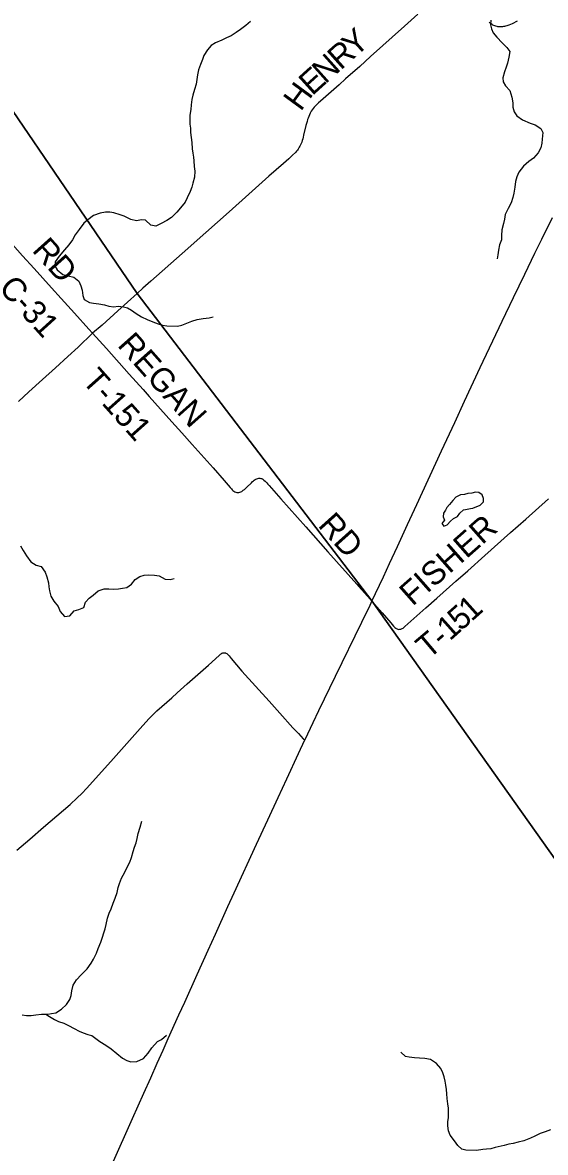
# Model space of a CAD drawing. Extents: x 0 to 34, y 0 to 22.
# Drawn here: x 27.52 to 28.78, y 16.977 to 19.7 of the extents above; entities that cross this region are included whole.
import ezdxf

# ---------------------------------------------------------------- set-up
doc = ezdxf.new("R2010")
doc.units = 0
for name, color, linetype in [('GM_X_Corporation', 7, 'Continuous'), ('GM_X_County_Road', 7, 'Continuous'), ('GM_X_County_Road_Text', 7, 'Continuous'), ('GM_X_Minor_Lake', 7, 'Continuous'), ('GM_X_Minor_River', 7, 'Continuous'), ('GM_X_State_Route', 7, 'Continuous'), ('GM_X_Township_Road', 7, 'Continuous'), ('GM_X_Township_Road_Text', 7, 'Continuous')]:
    doc.layers.add(name, color=color, linetype=linetype)

msp = doc.modelspace()

# ---------------------------------------------------------------- linework, layer by layer
at = {"layer": 'GM_X_Corporation'}
for points in [[(31.5875, 16.2767), (31.5875, 21.1059), (25.6086, 21.1059), (25.0178, 20.9472), (26.0175, 20.4289), (26.9873, 19.9283), (27.122, 19.8586), (27.3085, 19.7612), (27.7955, 19.0474), (28.3618, 18.3058), (29.4482, 16.7745), (29.7308, 16.376), (30.2965, 15.5727), (30.4064, 15.4161), (30.5426, 15.5161)], [(24.7875, 21.0754), (24.7875, 14.3059), (28.9316, 14.3059), (29.0116, 14.3654), (30.2271, 15.2782), (30.4064, 15.4161), (30.2965, 15.5727), (29.7308, 16.376), (29.4482, 16.7745), (28.3618, 18.3058), (27.7955, 19.0474), (27.3085, 19.7612), (27.122, 19.8586), (26.9873, 19.9283), (26.0175, 20.4289), (25.0178, 20.9472)]]:
    msp.add_lwpolyline(points, close=True, dxfattribs=at)
at = {"layer": 'GM_X_County_Road'}
for points in [[(28.4727, 19.7202), (28.4404, 19.6911), (28.3588, 19.6183), (28.3324, 19.5946), (28.2986, 19.5643), (28.2829, 19.5503), (28.238, 19.511), (28.2334, 19.5068), (28.2303, 19.5038), (28.2276, 19.501), (28.2251, 19.4985), (28.2229, 19.496), (28.2203, 19.4929), (28.2178, 19.4894), (28.2157, 19.4864), (28.2131, 19.4816), (28.2112, 19.4777), (28.2097, 19.4738), (28.2081, 19.4697), (28.2069, 19.4661), (28.2056, 19.462), (28.2029, 19.4518), (28.1973, 19.4283), (28.1961, 19.4239), (28.1951, 19.4198), (28.1939, 19.416), (28.1927, 19.412), (28.1913, 19.4085), (28.1897, 19.4051), (28.1884, 19.4022), (28.1867, 19.3995), (28.1857, 19.3978), (28.1841, 19.3953), (28.1822, 19.3928), (28.1802, 19.3903), (28.1774, 19.387), (28.1707, 19.3804), (28.1615, 19.372), (28.149, 19.3607), (28.1136, 19.3295), (28.0653, 19.2865), (28.0174, 19.2441), (27.9613, 19.194), (27.9046, 19.1437), (27.8289, 19.0764), (27.8098, 19.0596), (27.7958, 19.0469)], [(28.7119, 19.7035), (28.6997, 19.6973), (28.6922, 19.694), (28.6894, 19.693), (28.6869, 19.6921), (28.684, 19.6914), (28.6818, 19.6907), (28.6795, 19.6903), (28.677, 19.69), (28.6748, 19.6898), (28.6725, 19.6897), (28.6703, 19.6898), (28.6681, 19.6898), (28.6658, 19.6901), (28.6637, 19.6904), (28.6606, 19.6912), (28.6581, 19.6921), (28.6558, 19.6929), (28.6536, 19.694), (28.6515, 19.6953), (28.6492, 19.6968), (28.6469, 19.6987), (28.6449, 19.7004)], [(27.6884, 18.9512), (27.6794, 18.9612), (27.6446, 19), (27.6128, 19.035), (27.5895, 19.0608), (27.5681, 19.0842), (27.5474, 19.1073), (27.5192, 19.138), (27.4952, 19.165), (27.4895, 19.1714), (27.4847, 19.177), (27.4802, 19.1823), (27.4762, 19.1874), (27.4722, 19.1925), (27.4673, 19.1992), (27.4623, 19.206), (27.4369, 19.242), (27.4167, 19.2704), (27.3758, 19.3283), (27.3261, 19.3981), (27.2789, 19.4652), (27.2719, 19.4757)], [(27.7958, 19.0469), (27.7493, 19.0051), (27.7115, 18.9709), (27.6884, 18.9512)]]:
    msp.add_lwpolyline(points, dxfattribs=at)
at = {"layer": 'GM_X_Minor_Lake'}
for points in [[(28.5567, 18.5484), (28.5489, 18.5386), (28.5428, 18.531), (28.5393, 18.525), (28.5346, 18.5175), (28.5341, 18.5083), (28.5371, 18.5003), (28.5309, 18.4928), (28.5354, 18.4863), (28.543, 18.4892), (28.5511, 18.4983), (28.5588, 18.5043), (28.568, 18.5091), (28.5742, 18.5174), (28.5826, 18.5256), (28.5873, 18.5266)], [(28.5873, 18.5266), (28.5918, 18.5274), (28.5994, 18.5289), (28.6055, 18.5299), (28.6231, 18.5366), (28.6312, 18.5449), (28.6309, 18.5528), (28.6276, 18.5616), (28.62, 18.567), (28.6117, 18.5679), (28.6025, 18.5661), (28.5934, 18.5647), (28.585, 18.5628), (28.5755, 18.5618), (28.564, 18.5562), (28.5567, 18.5484)]]:
    msp.add_lwpolyline(points, dxfattribs=at)
at = {"layer": 'GM_X_Minor_River'}
for points in [[(28.0695, 19.7023), (28.0576, 19.6929), (28.0453, 19.6836), (28.0342, 19.6761), (28.0223, 19.6682), (28.0116, 19.6634), (28.0001, 19.6578), (27.9845, 19.6512), (27.9741, 19.6445), (27.9652, 19.6343), (27.9563, 19.6207), (27.9531, 19.6109), (27.9484, 19.5992), (27.9437, 19.5863), (27.9417, 19.5742), (27.94, 19.5628), (27.938, 19.5518), (27.9344, 19.5389), (27.93, 19.5249), (27.928, 19.5147), (27.9263, 19.5022), (27.9251, 19.4904), (27.923, 19.4767), (27.9225, 19.4653), (27.9231, 19.4551), (27.9241, 19.4452), (27.9248, 19.4353), (27.9258, 19.4228), (27.9275, 19.411), (27.9289, 19.3957), (27.9303, 19.3855), (27.9317, 19.376), (27.9327, 19.3665), (27.9337, 19.3535), (27.9347, 19.3417), (27.9345, 19.3277), (27.9305, 19.3129), (27.9277, 19.3031), (27.9238, 19.2925), (27.9164, 19.2777)], [(28.6483, 19.706), (28.6481, 19.6946), (28.6503, 19.6851), (28.654, 19.6752), (28.663, 19.6652), (28.6761, 19.6514), (28.6874, 19.6399), (28.6942, 19.6303), (28.6921, 19.617), (28.6885, 19.6026), (28.6857, 19.5924), (28.6818, 19.5814), (28.6774, 19.5666), (28.6784, 19.5571), (28.6844, 19.5476), (28.6942, 19.5364), (28.6989, 19.5201), (28.7014, 19.5063), (28.7021, 19.4965), (28.7053, 19.485), (28.7117, 19.4751)], [(28.7117, 19.4751), (28.7253, 19.4654), (28.7434, 19.4576), (28.7556, 19.4537), (28.7695, 19.4444), (28.7744, 19.4349), (28.7726, 19.4193), (28.7718, 19.4091), (28.769, 19.3985), (28.7631, 19.3864), (28.7512, 19.3736), (28.74, 19.365), (28.7273, 19.3537), (28.7161, 19.3394), (28.7111, 19.3281), (28.7083, 19.3167), (28.7066, 19.303), (28.7045, 19.289), (28.7017, 19.2788), (28.6974, 19.2655), (28.6907, 19.2519), (28.6829, 19.2372), (28.6813, 19.2266), (28.6789, 19.2156), (28.6749, 19.2008), (28.674, 19.1872), (28.6742, 19.1761), (28.6699, 19.164), (28.6674, 19.1511), (28.6654, 19.1405), (28.6638, 19.1307)], [(27.9164, 19.2777), (27.9113, 19.2675), (27.9005, 19.2536), (27.8916, 19.2431), (27.8785, 19.2299), (27.8674, 19.2232), (27.8536, 19.2161), (27.841, 19.2094), (27.8289, 19.2115), (27.8157, 19.2238), (27.8062, 19.2243), (27.794, 19.2225), (27.7803, 19.2253), (27.7648, 19.2335), (27.755, 19.237), (27.7394, 19.2417), (27.7296, 19.243), (27.7193, 19.2431), (27.7067, 19.241), (27.6906, 19.2347), (27.6772, 19.2242), (27.6672, 19.2167), (27.656, 19.2016), (27.6463, 19.1881), (27.6397, 19.1767), (27.6312, 19.1647), (27.6204, 19.1526), (27.608, 19.1368), (27.598, 19.1233), (27.5971, 19.1138), (27.6031, 19.1038), (27.6166, 19.0927), (27.6299, 19.0895), (27.6428, 19.0863), (27.6556, 19.0766), (27.6601, 19.0652), (27.663, 19.0549), (27.6651, 19.042), (27.6684, 19.0324), (27.6809, 19.0255), (27.6908, 19.0234), (27.7033, 19.0222), (27.717, 19.0194), (27.7272, 19.0166), (27.7397, 19.0145), (27.7504, 19.0163), (27.7626, 19.015), (27.7724, 19.0123), (27.7822, 19.0065), (27.7932, 18.9991), (27.806, 18.9906), (27.8196, 18.9844), (27.8337, 18.9785), (27.8469, 18.9738), (27.8568, 18.9707), (27.8674, 18.9687), (27.8933, 18.9684), (27.9036, 18.9709), (27.9158, 18.9757), (27.9276, 18.9801), (27.9402, 18.9842), (27.9551, 18.9871), (27.9692, 18.9884), (27.9788, 18.9906)], [(27.5147, 18.4388), (27.5211, 18.4274), (27.5289, 18.4144), (27.5398, 18.4002), (27.5526, 18.3925), (27.5647, 18.3889), (27.5737, 18.3751), (27.5781, 18.3644), (27.5818, 18.3492), (27.5828, 18.3397), (27.5842, 18.3302), (27.5879, 18.3176), (27.5953, 18.3054), (27.6054, 18.2923), (27.6102, 18.2801), (27.6204, 18.2682), (27.6337, 18.2704), (27.6437, 18.2824), (27.6556, 18.2853), (27.667, 18.2905), (27.671, 18.303), (27.6799, 18.3128), (27.6899, 18.3199), (27.7018, 18.33), (27.7163, 18.3348), (27.7277, 18.335), (27.7383, 18.3345), (27.7505, 18.3355), (27.7608, 18.3366), (27.7707, 18.3384), (27.7826, 18.3462), (27.7911, 18.3575), (27.8026, 18.365), (27.8129, 18.3679), (27.8244, 18.3685), (27.8377, 18.3684), (27.8491, 18.3663), (27.8634, 18.3582), (27.8752, 18.3577), (27.8851, 18.3602)], [(27.7986, 17.745), (27.8029, 17.7609), (27.8073, 17.7753)], [(27.5186, 17.3082), (27.5288, 17.307), (27.5402, 17.3068), (27.5513, 17.3082), (27.565, 17.31), (27.5802, 17.3102), (27.5897, 17.3112), (27.6, 17.3134), (27.6138, 17.322), (27.6254, 17.3333), (27.6339, 17.3449), (27.6367, 17.3548), (27.638, 17.3662), (27.6412, 17.3798), (27.6497, 17.3926), (27.6609, 17.405), (27.6751, 17.4193), (27.6852, 17.4329), (27.6906, 17.4427), (27.6977, 17.4571), (27.702, 17.468), (27.7083, 17.4835), (27.7126, 17.4956), (27.7154, 17.5059), (27.7185, 17.5157), (27.7213, 17.5259), (27.7246, 17.5411), (27.7285, 17.5536), (27.7328, 17.5638), (27.7379, 17.5774), (27.743, 17.5895), (27.7474, 17.6028), (27.7502, 17.6149), (27.7533, 17.6251), (27.7585, 17.638), (27.7658, 17.6519), (27.7725, 17.6659), (27.7779, 17.6761), (27.7819, 17.6871), (27.7862, 17.7019), (27.7894, 17.7121), (27.7937, 17.723), (27.7961, 17.7329), (27.7986, 17.745)], [(27.5756, 17.3101), (27.5847, 17.3045), (27.5968, 17.2967), (27.6066, 17.2924), (27.6188, 17.2881), (27.6301, 17.2827), (27.6437, 17.2757), (27.6558, 17.2687), (27.6657, 17.2648), (27.677, 17.2609), (27.6865, 17.2581), (27.7061, 17.2442), (27.7201, 17.2349), (27.7329, 17.2264), (27.7465, 17.2149), (27.7608, 17.2037), (27.7706, 17.1979), (27.7805, 17.1948), (27.7949, 17.1957), (27.8114, 17.2028), (27.8222, 17.2156), (27.8311, 17.2291), (27.8446, 17.2438), (27.8542, 17.249), (27.8669, 17.2591)], [(28.7928, 17.0314), (28.7795, 17.0266), (28.768, 17.0218), (28.755, 17.0155), (28.7443, 17.0107), (28.7286, 17.0048), (28.7148, 17.0015), (28.7026, 16.9983), (28.6923, 16.9961), (28.6809, 16.9936), (28.6595, 16.9885), (28.6488, 16.9856), (28.6385, 16.9842), (28.629, 16.9839), (28.6142, 16.9814), (28.5887, 16.9817), (28.5788, 16.9848), (28.569, 16.9929), (28.5612, 17.0044), (28.5507, 17.0182), (28.5463, 17.0289), (28.5449, 17.0407), (28.545, 17.0506), (28.5463, 17.0608), (28.5464, 17.073), (28.5462, 17.0836), (28.5451, 17.0935), (28.543, 17.1064), (28.5428, 17.1182), (28.5421, 17.1281), (28.5404, 17.1384), (28.5386, 17.1483), (28.5364, 17.1589), (28.5327, 17.1685), (28.5283, 17.1791), (28.5174, 17.191), (28.5031, 17.2007), (28.4898, 17.2031), (28.4768, 17.204), (28.4647, 17.2046), (28.4521, 17.2058), (28.4426, 17.2075), (28.4317, 17.2182)]]:
    msp.add_lwpolyline(points, dxfattribs=at)
at = {"layer": 'GM_X_State_Route'}
for points in [[(28.362, 18.3053), (28.3705, 18.3237), (28.3895, 18.3642), (28.4044, 18.3963), (28.4235, 18.4368), (28.448, 18.4905), (28.4702, 18.5384), (28.5298, 18.6676), (28.5616, 18.7364), (28.5852, 18.7878), (28.6228, 18.8683), (28.676, 18.98), (28.7032, 19.0372), (28.7305, 19.0937), (28.7548, 19.144), (28.7717, 19.178), (28.7974, 19.2304)], [(27.7354, 16.9479), (27.7845, 17.058), (27.8123, 17.1198), (27.8286, 17.1567), (27.8445, 17.1918), (27.8585, 17.223), (27.8706, 17.2509), (27.8966, 17.308), (27.911, 17.339), (27.9408, 17.4053), (27.9674, 17.4642), (27.9846, 17.5028), (28.0146, 17.5697), (28.0298, 17.6024), (28.0835, 17.7199), (28.1108, 17.7785), (28.1355, 17.8321), (28.1564, 17.8772), (28.1852, 17.9378), (28.2005, 17.971), (28.2011, 17.9722), (28.2199, 18.0128), (28.2337, 18.042), (28.274, 18.1247), (28.3377, 18.2547), (28.3492, 18.2781), (28.3559, 18.2921), (28.362, 18.3053)]]:
    msp.add_lwpolyline(points, dxfattribs=at)
at = {"layer": 'GM_X_Township_Road'}
for points in [[(27.5098, 18.7865), (27.535, 18.8096), (27.568, 18.8398), (27.5988, 18.8678), (27.6286, 18.895), (27.6535, 18.9176), (27.6884, 18.9512)], [(27.6884, 18.9512), (27.7216, 18.9146), (27.7769, 18.8524), (27.8101, 18.8153), (27.8246, 18.7991), (27.8797, 18.7375), (27.9033, 18.711), (27.9283, 18.6834), (27.9789, 18.6269), (28.0059, 18.596), (28.0104, 18.5909), (28.0205, 18.5791), (28.0233, 18.5758), (28.0249, 18.574), (28.0267, 18.5723), (28.0286, 18.5708), (28.0311, 18.5692), (28.0339, 18.5681), (28.0361, 18.5675), (28.0382, 18.567), (28.0407, 18.5671), (28.0436, 18.5678), (28.046, 18.5686), (28.0479, 18.5697), (28.0501, 18.571), (28.0518, 18.5726), (28.0546, 18.5749), (28.0601, 18.58), (28.0713, 18.5908), (28.074, 18.5935), (28.0762, 18.5953), (28.0784, 18.5972), (28.0805, 18.5986), (28.0824, 18.5997), (28.0843, 18.6006), (28.0868, 18.6012), (28.0892, 18.6016), (28.0916, 18.6015), (28.0938, 18.6013), (28.0959, 18.6008), (28.097, 18.6003), (28.0981, 18.5999), (28.0999, 18.5984), (28.1016, 18.5971), (28.1044, 18.5946), (28.1084, 18.5905), (28.1109, 18.5876), (28.1142, 18.5839), (28.142, 18.5521), (28.2023, 18.4842), (28.2555, 18.4243), (28.3255, 18.346), (28.33, 18.3409), (28.3575, 18.3103), (28.362, 18.3053)], [(28.362, 18.3053), (28.387, 18.2769), (28.4076, 18.2528), (28.414, 18.2452), (28.4175, 18.2417), (28.4195, 18.2403), (28.4201, 18.2399), (28.4208, 18.2394), (28.4226, 18.2385), (28.4248, 18.2377), (28.427, 18.2373), (28.4293, 18.2375), (28.4313, 18.238), (28.4329, 18.2386), (28.4347, 18.2393), (28.437, 18.2407), (28.4416, 18.2442), (28.4486, 18.2504), (28.492, 18.2895), (28.5185, 18.313), (28.5641, 18.3533), (28.5929, 18.3789), (28.6342, 18.4157), (28.6963, 18.4711), (28.7332, 18.5034), (28.7879, 18.5523)], [(27.506, 17.7048), (27.537, 17.7316), (27.5704, 17.7604), (27.6344, 17.8156), (27.6515, 17.831), (27.6627, 17.8418), (27.6746, 17.8544), (27.7387, 17.9263), (27.8031, 17.9988), (27.8239, 18.0219), (27.8335, 18.0316), (27.8435, 18.0409), (27.8794, 18.0726), (27.8923, 18.0843), (27.9164, 18.1058), (27.9675, 18.1512), (27.9933, 18.1745), (27.9971, 18.1777), (27.9984, 18.1787), (27.9993, 18.1793), (28.0002, 18.1799), (28.0009, 18.1803), (28.0023, 18.1808), (28.0031, 18.181), (28.0043, 18.1812), (28.005, 18.1812), (28.0065, 18.1812), (28.0074, 18.181), (28.0087, 18.1806), (28.01, 18.1801), (28.0117, 18.1792), (28.0128, 18.1784), (28.0144, 18.177), (28.0156, 18.1759), (28.0178, 18.1735), (28.0229, 18.1674), (28.0485, 18.137), (28.0813, 18.1005), (28.1142, 18.064), (28.1402, 18.0355), (28.1716, 18.0003), (28.1846, 17.9861), (28.1963, 17.9737), (28.1971, 17.973), (28.1985, 17.9722), (28.2005, 17.971)]]:
    msp.add_lwpolyline(points, dxfattribs=at)

# ---------------------------------------------------------------- texts
at = {"layer": 'GM_X_County_Road_Text'}
for s, height, rotation, p in [('Y', 0.0568, 41.7648, (28.3213, 19.615)), ('R', 0.0568, 41.7554, (28.2865, 19.584)), ('N', 0.0568, 41.7606, (28.2492, 19.5507)), ('E', 0.0568, 42.0563, (28.2177, 19.5222)), ('H', 0.0568, 53.761, (28.1902, 19.4842)), ('RD', 0.05682, 311.84, (27.5404, 19.1499)), ('C-31', 0.05682, 312.0926, (27.4598, 19.0587))]:
    msp.add_text(s, height=height, rotation=rotation, dxfattribs=at).set_placement(p)
at = {"layer": 'GM_X_Township_Road_Text'}
for s, height, rotation, p in [('REGAN', 0.05682, 311.6322, (27.7463, 18.9214)), ('T-151', 0.05682, 311.6778, (27.6607, 18.8354)), ('RD', 0.05682, 311.8748, (28.2298, 18.4871)), ('FISHER', 0.05682, 41.3889, (28.4598, 18.2918)), ('1', 0.0568, 41.8303, (28.602, 18.2548)), ('5', 0.0568, 41.8211, (28.5759, 18.2315)), ('1', 0.0568, 41.7351, (28.5497, 18.2081)), ('T', 0.0568, 40.2308, (28.4986, 18.1642)), ('-', 0.0568, 41.5256, (28.5321, 18.1925))]:
    msp.add_text(s, height=height, rotation=rotation, dxfattribs=at).set_placement(p)

doc.saveas('drawing.dxf')
